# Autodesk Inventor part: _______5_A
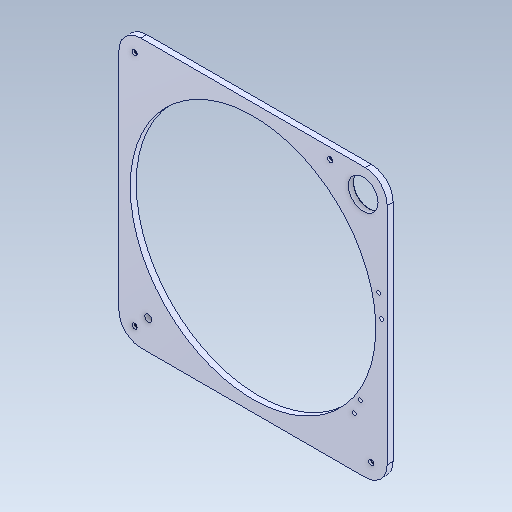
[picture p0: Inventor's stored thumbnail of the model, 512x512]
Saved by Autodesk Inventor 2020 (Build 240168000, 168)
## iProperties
Created: 2017-09
Part Number: _______5_A
Material: Générique
Document SubType Name: Modeling
Designer: bruno
Density: 1 g/cm^3
Appearance: Par défaut
Author: bruno
Sending System: SolidWorks 2016
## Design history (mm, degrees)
feature "Importée1"
node "Solide1"
